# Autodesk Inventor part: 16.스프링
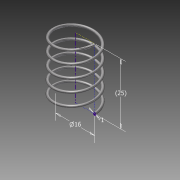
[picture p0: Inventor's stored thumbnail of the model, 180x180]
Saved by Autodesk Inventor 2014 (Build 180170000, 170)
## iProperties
Created: 2015-11
Part Number: 16.스프링
Material: 강철, 탄소
Document SubType Name: Modeling
Designer: SEC
Mass: 1.5393 g
Surface Area: 7.90158 cm^2
Volume: 0.195591 cm^3
Density: 7.87 g/cm^3
Appearance: 반연마
Author: SEC
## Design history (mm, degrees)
sketch "스케치1"
  geometry: L1 (0, 0)-(8, 0); L2 (8, 0)-(8, 26); L3 (8, 26)-(0, 26); L4 (0, 26)-(0, 0); C1 r 0.5 at (8, 0)
  constraints: 8 end point, 2 parallel, 1 centre point, 1 coincident, 1 horizontal, 1 perpendicular
  dimensions: "d1" = 16 diameter of L2 L4; "d2" = 26 distance of L1.end L2.end (derived); "d3" = 1 diameter of C1
feature "코일1" pitch "d4" = 10; turns "d6" = 5; dims "d5" = 26 (= d2), "d7" = 0, angle "d8" = 90 deg, angle "d9" = 90 deg, "d10" = 0, "d11" = 0
sketch "스케치2"
  geometry: L1 (-8.5, 0)-(-7.5, 0) reference; 1 further point
  constraints: 1 horizontal alignment
extrude "돌출1" cut sketch "스케치2" stored distance "d12" = 10; taper "d13" = 0 deg
node "작업 평면2"
sketch "스케치3"
  geometry: L1 (0.5, 0)-(-0.5, 0) reference; 1 further point
  constraints: 1 horizontal alignment
extrude "돌출2" cut sketch "스케치3" stored distance "d15" = 10; taper "d16" = 0 deg
node "솔리드1"
node "절단 모서리 투영1"
node "절단 모서리 투영2"
other parameters: "d14" = 0
